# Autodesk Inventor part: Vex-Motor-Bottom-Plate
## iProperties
Created: 2007-08
Part Number: Vex-Motor-Bottom-Plate
Material: ABS Plastic
Document SubType Name: Modeling
Density: 1.06 g/cm^3
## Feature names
1. Base1
